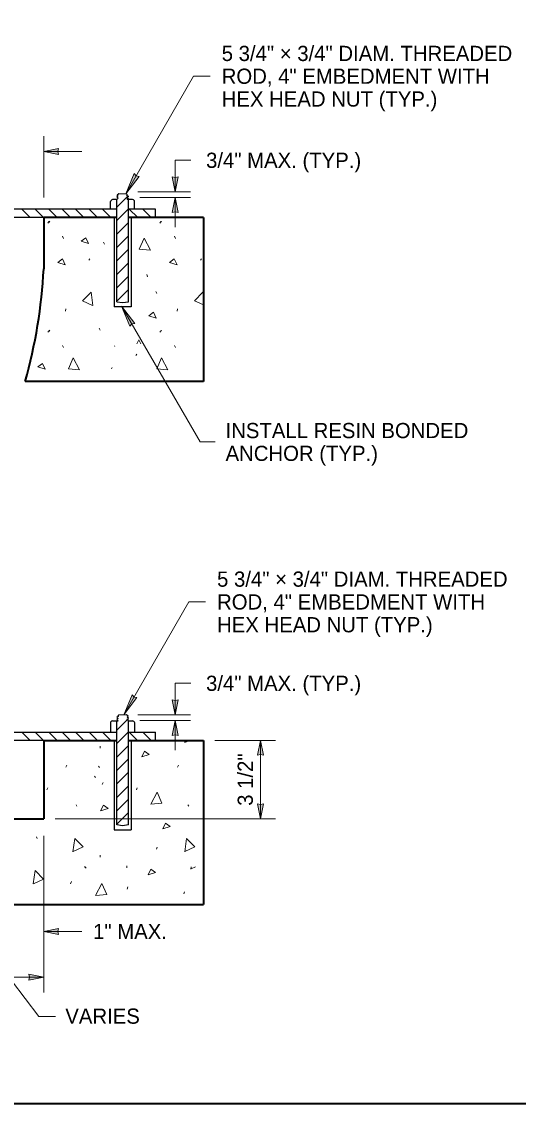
# Model space of a CAD drawing. Extents: x 99860 to 103153, y 99998 to 102077.
# Drawn here: x 100819 to 101342, y 100000 to 101138 of the extents above; entities that cross this region are included whole.
import ezdxf
from ezdxf.enums import TextEntityAlignment as Align

# ---------------------------------------------------------------- set-up
doc = ezdxf.new("R2010")
doc.units = 0
doc.header["$LTSCALE"] = 6.4
for name, color, linetype, lineweight in [('1', 7, 'Continuous', 13), ('13', 7, 'Continuous', 40), ('15', 7, 'Continuous', 13), ('17', 7, 'Continuous', 13), ('18', 7, 'Continuous', 13), ('20', 7, 'Continuous', 13)]:
    doc.layers.add(name, color=color, linetype=linetype, lineweight=lineweight)

msp = doc.modelspace()

# ---------------------------------------------------------------- hatches: boundary and pattern name
at = {"layer": '15'}
for points in [[(100842.512, 101001.29), (100858.237, 100998.206), (100857.509, 101001.29), (100858.237, 101004.374)], [(100928.847, 100956.8), (100942.847, 100975.078), (100939.734, 100975.656), (100937.677, 100978.063)], [(100980.932, 100958.794), (100984.016, 100974.519), (100980.932, 100973.791), (100977.848, 100974.519)], [(100980.932, 100952.864), (100977.848, 100937.139), (100980.932, 100937.867), (100984.016, 100937.139)], [(100924.492, 100838.624), (100938.491, 100820.346), (100935.377, 100819.77), (100933.321, 100817.361)], [(100926.711, 100408.306), (100940.711, 100426.584), (100937.598, 100427.162), (100935.541, 100429.569)], [(100980.922, 100408.355), (100984.006, 100424.08), (100980.922, 100423.352), (100977.838, 100424.08)], [(100980.922, 100402.425), (100977.838, 100386.7), (100980.922, 100387.428), (100984.006, 100386.7)], [(101070.7, 100381.515), (101067.616, 100365.79), (101070.7, 100366.518), (101073.784, 100365.79)], [(101070.7, 100298.945), (101073.784, 100314.67), (101070.7, 100313.942), (101067.616, 100314.67)], [(100842.502, 100180.375), (100858.227, 100177.291), (100857.499, 100180.375), (100858.227, 100183.459)], [(100842.502, 100132.309), (100826.777, 100129.225), (100827.505, 100132.309), (100826.777, 100135.393)]]:
    msp.add_hatch(color=256, dxfattribs=at).paths.add_polyline_path(points)

# ---------------------------------------------------------------- linework, layer by layer
at = {"layer": '1', "lineweight": 25}
for p, q in [((100912.812, 100940.734), (100912.812, 100948.694)), ((100919.625, 100950.704), (100915.022, 100950.704)), ((100919.862, 100950.564), (100919.442, 100950.834)), ((100919.482, 100843.193), (100919.482, 100950.704)), ((100921.592, 100956.924), (100929.762, 100956.784)), ((100929.762, 100956.784), (100930.452, 100956.094)), ((100930.452, 100956.094), (100929.762, 100955.544)), ((100935.912, 100950.704), (100930.256, 100950.704)), ((100931.762, 100843.193), (100931.762, 100950.704)), ((100937.922, 100940.734), (100937.922, 100949.594)), ((100919.482, 100940.734), (100724.902, 100940.734)), ((100960.132, 100940.734), (100931.762, 100940.734)), ((100960.132, 100931.954), (100960.132, 100940.734)), ((100842.522, 100931.954), (100278.932, 100931.954)), ((100916.828, 100931.954), (100916.828, 100837.8)), ((100934.468, 100931.954), (100934.468, 100837.8)), ((100934.468, 100837.8), (100916.828, 100837.8)), ((100913.242, 100390.295), (100913.242, 100401.015)), ((100915.252, 100402.125), (100921.028, 100402.125)), ((100921.402, 100408.215), (100920.712, 100407.455)), ((100920.712, 100407.455), (100921.402, 100406.975)), ((100929.572, 100408.355), (100921.402, 100408.215)), ((100931.502, 100402.125), (100931.712, 100402.335)), ((100931.502, 100402.125), (100936.142, 100402.125)), ((100931.752, 100292.698), (100931.752, 100402.125)), ((100938.352, 100390.295), (100938.352, 100400.125)), ((100724.892, 100390.295), (100919.472, 100390.295)), ((100931.752, 100390.295), (100960.122, 100390.295)), ((100931.752, 100381.515), (100931.752, 100390.295)), ((100960.122, 100381.515), (100960.122, 100390.295)), ((100842.502, 100381.515), (100278.942, 100381.515)), ((100916.766, 100381.459), (100916.766, 100287.305)), ((100934.406, 100381.459), (100934.406, 100287.305)), ((100916.766, 100287.305), (100934.406, 100287.305))]:
    msp.add_line(p, q, dxfattribs=at)
at = {"layer": '1', "lineweight": 35}
msp.add_lwpolyline([(99862, 99999.5), (103151, 99999.5), (103151, 102075.5), (99862, 102075.5)], close=True, dxfattribs=at)
at = {"layer": '1', "lineweight": 25}
for points in [[(100919.442, 100950.834), (100921.042, 100952.084), (100919.512, 100953.534), (100920.902, 100954.364), (100919.792, 100955.544), (100921.592, 100956.924)], [(100929.762, 100955.544), (100931.692, 100953.954), (100930.172, 100953.184), (100931.692, 100951.744), (100930.032, 100950.634)], [(100919.482, 100843.193), (100925.622, 100842.229), (100931.762, 100843.193)], [(100921.402, 100406.975), (100919.472, 100405.455), (100920.992, 100404.615), (100919.472, 100403.165), (100921.028, 100402.125)], [(100931.752, 100292.698), (100925.612, 100291.734), (100919.472, 100292.698), (100919.472, 100402.125)], [(100931.712, 100402.335), (100930.122, 100403.515), (100931.642, 100404.965), (100930.262, 100405.865), (100931.372, 100406.975), (100929.572, 100408.355)]]:
    msp.add_lwpolyline(points, dxfattribs=at)
for centre, radius, start, end in [((100916.475, 100946.794), 4.132, 110.20557, 152.52832), ((100935.933, 100948.343), 2.325, 32.69635, 91.70415), ((100915.234, 100399.771), 2.325, 88.29585, 147.30365), ((100934.692, 100398.222), 4.132, 27.47168, 69.79443)]:
    msp.add_arc(centre, radius, start, end, dxfattribs=at)
at = {"layer": '13'}
for p, q in [((100842.522, 100931.954), (100842.522, 100877.934)), ((100919.482, 100931.954), (100842.522, 100931.954)), ((101010.747, 100931.954), (100931.762, 100931.954)), ((101010.747, 100931.954), (101010.747, 100759.144)), ((101010.747, 100759.144), (100822.905, 100759.144)), ((100842.502, 100381.515), (100919.472, 100381.515)), ((100842.502, 100381.515), (100842.502, 100298.945)), ((100931.752, 100381.515), (101010.727, 100381.515)), ((101010.727, 100381.515), (101010.727, 100208.705)), ((100769.422, 100298.945), (100842.502, 100298.945)), ((100649.652, 100208.705), (101010.727, 100208.705))]:
    msp.add_line(p, q, dxfattribs=at)
msp.add_arc((100309.501, 100904.944), 533.705, 344.14616, 357.09911, dxfattribs=at)
at = {"layer": '15'}
for p, q in [((100928.847, 100956.8), (101000.266, 101080.5)), ((101000.266, 101080.5), (101017.9, 101080.5)), ((100842.512, 101017.29), (100842.512, 100952.734)), ((100842.512, 101001.29), (100882.502, 101001.29)), ((100941.582, 100958.794), (100996.932, 100958.794)), ((100943.762, 100952.864), (100996.932, 100952.864)), ((100980.932, 100921.628), (100980.932, 100952.864)), ((100926.711, 100408.306), (100995.382, 100527.247)), ((100995.382, 100527.247), (101013.016, 100527.247)), ((100941.572, 100408.355), (100996.922, 100408.355)), ((100943.752, 100402.425), (100996.922, 100402.425)), ((100980.922, 100371.189), (100980.922, 100402.425)), ((101022.727, 100381.515), (101086.7, 100381.515)), ((101070.7, 100381.515), (101070.7, 100298.945)), ((100854.502, 100298.945), (101086.7, 100298.945)), ((100842.502, 100281.159), (100842.502, 100116.309)), ((100882.492, 100180.375), (100842.502, 100180.375)), ((100842.502, 100132.309), (100769.422, 100132.309)), ((100808.716, 100128.67), (100837.27, 100090.939)), ((100837.27, 100090.939), (100854.904, 100090.939))]:
    msp.add_line(p, q, dxfattribs=at)
for points in [[(100842.512, 101001.29), (100858.237, 100998.206), (100857.509, 101001.29), (100858.237, 101004.374)], [(100928.847, 100956.8), (100942.847, 100975.078), (100939.734, 100975.656), (100937.677, 100978.063)], [(100980.932, 100958.794), (100984.016, 100974.519), (100980.932, 100973.791), (100977.848, 100974.519)], [(100980.932, 100952.864), (100977.848, 100937.139), (100980.932, 100937.867), (100984.016, 100937.139)], [(100924.492, 100838.624), (100938.491, 100820.346), (100935.377, 100819.77), (100933.321, 100817.361)], [(100926.711, 100408.306), (100940.711, 100426.584), (100937.598, 100427.162), (100935.541, 100429.569)], [(100980.922, 100408.355), (100984.006, 100424.08), (100980.922, 100423.352), (100977.838, 100424.08)], [(100980.922, 100402.425), (100977.838, 100386.7), (100980.922, 100387.428), (100984.006, 100386.7)], [(101070.7, 100381.515), (101067.616, 100365.79), (101070.7, 100366.518), (101073.784, 100365.79)], [(101070.7, 100298.945), (101073.784, 100314.67), (101070.7, 100313.942), (101067.616, 100314.67)], [(100842.502, 100180.375), (100858.227, 100177.291), (100857.499, 100180.375), (100858.227, 100183.459)], [(100842.502, 100132.309), (100826.777, 100129.225), (100827.505, 100132.309), (100826.777, 100135.393)]]:
    msp.add_lwpolyline(points, close=True, dxfattribs=at)
for points in [[(100980.932, 100958.794), (100980.932, 100992.034), (100997.422, 100992.034)], [(100924.491, 100838.625), (101007.069, 100695.594), (101023.069, 100695.594)], [(100980.922, 100408.355), (100980.922, 100441.595), (100997.412, 100441.595)]]:
    msp.add_lwpolyline(points, dxfattribs=at)
at = {"layer": '17'}
for p, q in [((100847.982, 100927.454), (100847.012, 100926.004)), ((100848.952, 100928.004), (100847.982, 100926.554)), ((100965.662, 100927.454), (100964.702, 100926.004)), ((100966.632, 100928.004), (100965.662, 100926.554)), ((100863.482, 100909.814), (100862.442, 100912.024)), ((100906.442, 100903.654), (100905.472, 100905.864)), ((100981.162, 100909.814), (100980.192, 100912.024)), ((100890.942, 100888.434), (100889.982, 100886.984)), ((101008.692, 100888.434), (101007.722, 100886.984)), ((100951.902, 100869.544), (100950.922, 100871.764)), ((100961.512, 100851.834), (100960.542, 100854.054)), ((100865.692, 100835.574), (100865.482, 100833.364)), ((100983.442, 100835.574), (100983.162, 100833.364)), ((100847.982, 100812.684), (100847.012, 100811.224)), ((100848.952, 100813.234), (100847.982, 100811.774)), ((100901.802, 100813.234), (100900.762, 100815.444)), ((100965.662, 100812.684), (100964.702, 100811.224)), ((100966.632, 100813.234), (100965.662, 100811.774)), ((100863.482, 100795.034), (100862.442, 100797.244)), ((100917.442, 100796.144), (100917.092, 100796.904)), ((100940.538, 100787.958), (100939.568, 100786.508)), ((100981.162, 100795.034), (100980.192, 100797.244)), ((100914.705, 100774.048), (100913.735, 100772.598)), ((100990.972, 100379.225), (100991.322, 100381.515)), ((100996.022, 100381.515), (100991.252, 100379.295)), ((100901.802, 100375.565), (100902.072, 100373.345)), ((100865.752, 100353.215), (100866.722, 100355.425)), ((100983.432, 100353.215), (100984.472, 100355.425)), ((100896.122, 100343.875), (100897.092, 100342.425)), ((100900.342, 100354.395), (100901.312, 100352.935)), ((100904.082, 100335.015), (100905.052, 100337.235)), ((100845.832, 100329.345), (100846.802, 100331.555)), ((100940.062, 100329.345), (100941.022, 100331.555)), ((100876.542, 100313.645), (100877.512, 100312.185)), ((100994.292, 100313.645), (100995.272, 100312.185)), ((100834.776, 100279.864), (100835.736, 100278.404)), ((100961.082, 100266.945), (100962.062, 100269.155)), ((100901.802, 100260.785), (100902.072, 100258.575)), ((100885.269, 100248.89), (100886.239, 100247.44)), ((100886.239, 100248.34), (100887.199, 100246.88)), ((100929.904, 100249.509), (100930.124, 100247.289)), ((100997.452, 100246.086), (100997.792, 100248.376)), ((101002.432, 100248.376), (100997.652, 100246.156)), ((100870.739, 100230.69), (100871.779, 100232.91)), ((100930.239, 100225.02), (100931.209, 100227.23)), ((100989.902, 100220.076), (100990.872, 100222.286))]:
    msp.add_line(p, q, dxfattribs=at)
for points in [[(100889.702, 100904.484), (100886.792, 100910.574), (100881.882, 100906.904)], [(100865.142, 100882.074), (100862.232, 100888.154), (100857.322, 100884.494)], [(100982.892, 100882.074), (100979.922, 100888.154), (100975.002, 100884.494)], [(100961.032, 100826.034), (100958.052, 100832.114), (100953.142, 100828.454)], [(100844.073, 100772.241), (100841.093, 100778.321), (100836.183, 100774.661)], [(100945.667, 100364.154), (100948.647, 100370.304), (100953.557, 100366.574)], [(100902.352, 100307.275), (100905.332, 100313.365), (100910.232, 100309.695)], [(100967.991, 100288.347), (100970.901, 100294.437), (100975.811, 100290.767)], [(100952.324, 100239.959), (100955.234, 100246.119), (100960.144, 100242.379)]]:
    msp.add_lwpolyline(points, close=True, dxfattribs=at)
for points in [[(100954.872, 100897.494), (100948.232, 100910.014), (100943.042, 100898.534), (100954.592, 100897.494)], [(100894.262, 100839.174), (100892.332, 100853.214), (100883.472, 100844.154), (100893.992, 100839.244)], [(101010.012, 100853.214), (101001.222, 100844.154), (101009.942, 100840.084)], [(100944.912, 100798.704), (100942.562, 100803.134), (100940.552, 100798.704)], [(100880.242, 100771.432), (100873.602, 100783.952), (100868.482, 100772.472), (100880.032, 100771.432)], [(100973.195, 100771.432), (100966.555, 100783.952), (100961.435, 100772.472), (100972.985, 100771.432)], [(100955.178, 100314.358), (100961.818, 100326.888), (100967.008, 100315.398), (100955.458, 100314.358)], [(100873.292, 100264.385), (100875.232, 100278.425), (100884.012, 100269.365), (100873.502, 100264.455)], [(100990.972, 100264.385), (100992.912, 100278.425), (101001.772, 100269.365), (100991.252, 100264.455)], [(100831.526, 100230.604), (100833.456, 100244.644), (100842.246, 100235.584), (100831.726, 100230.674)], [(100897.099, 100218.38), (100903.739, 100230.9), (100908.859, 100219.42), (100897.309, 100218.38)]]:
    msp.add_lwpolyline(points, dxfattribs=at)
at = {"layer": '18'}
for p, q in [((100930.483, 100953.694), (100919.482, 100942.693)), ((100828.287, 100931.954), (100819.507, 100940.734)), ((100842.429, 100931.954), (100833.649, 100940.734)), ((100856.571, 100931.954), (100847.791, 100940.734)), ((100870.714, 100931.954), (100861.934, 100940.734)), ((100884.856, 100931.954), (100876.076, 100940.734)), ((100898.998, 100931.954), (100890.218, 100940.734)), ((100913.14, 100931.954), (100904.36, 100940.734)), ((100931.762, 100940.831), (100919.482, 100928.551)), ((100941.424, 100931.954), (100932.644, 100940.734)), ((100955.566, 100931.954), (100946.786, 100940.734)), ((100931.762, 100926.689), (100919.482, 100914.409)), ((100931.762, 100912.547), (100919.482, 100900.267)), ((100931.762, 100898.405), (100919.482, 100886.124)), ((100931.762, 100884.262), (100919.482, 100871.982)), ((100931.762, 100870.12), (100919.482, 100857.84)), ((100931.762, 100855.978), (100919.482, 100843.698)), ((100930.473, 100403.255), (100919.472, 100392.254)), ((100828.277, 100381.515), (100819.497, 100390.295)), ((100842.419, 100381.515), (100833.639, 100390.295)), ((100856.561, 100381.515), (100847.781, 100390.295)), ((100870.704, 100381.515), (100861.924, 100390.295)), ((100884.846, 100381.515), (100876.066, 100390.295)), ((100898.988, 100381.515), (100890.208, 100390.295)), ((100913.13, 100381.515), (100904.35, 100390.295)), ((100919.472, 100389.315), (100918.492, 100390.295)), ((100931.752, 100390.392), (100919.472, 100378.112)), ((100941.414, 100381.515), (100932.634, 100390.295)), ((100955.556, 100381.515), (100946.776, 100390.295)), ((100931.752, 100376.25), (100919.472, 100363.97)), ((100931.752, 100362.108), (100919.472, 100349.828)), ((100931.752, 100347.966), (100919.472, 100335.685)), ((100931.752, 100333.823), (100919.472, 100321.543)), ((100931.752, 100319.681), (100919.472, 100307.401)), ((100931.752, 100305.539), (100919.472, 100293.259))]:
    msp.add_line(p, q, dxfattribs=at)

# ---------------------------------------------------------------- texts
at = {"layer": '20'}
for s, p in [('5 3/4" × 3/4" DIAM. THREADED', (101029.9, 101096.5)), ('ROD, 4" EMBEDMENT WITH', (101029.9, 101072.5)), ('HEX HEAD NUT (TYP.)', (101029.9, 101048.5)), ('3/4" MAX. (TYP.)', (101013.422, 100984.034)), ('INSTALL RESIN BONDED', (101033.964, 100699.594)), ('ANCHOR (TYP.)', (101033.964, 100675.594)), ('5 3/4" × 3/4" DIAM. THREADED', (101025.016, 100543.247)), ('ROD, 4" EMBEDMENT WITH', (101025.016, 100519.247)), ('HEX HEAD NUT (TYP.)', (101025.016, 100495.247)), ('3/4" MAX. (TYP.)', (101013.412, 100433.595)), ('1" MAX.', (100894.492, 100172.375))]:
    msp.add_text(s, height=16, dxfattribs=at).set_placement(p)
msp.add_text('3 1/2"', height=16, rotation=90, dxfattribs=at).set_placement((101062.7, 100340.232), align=Align.CENTER)
msp.add_text('VARIES', height=16, dxfattribs=at).set_placement((100904.484, 100083.318), align=Align.CENTER)

doc.saveas('drawing.dxf')
